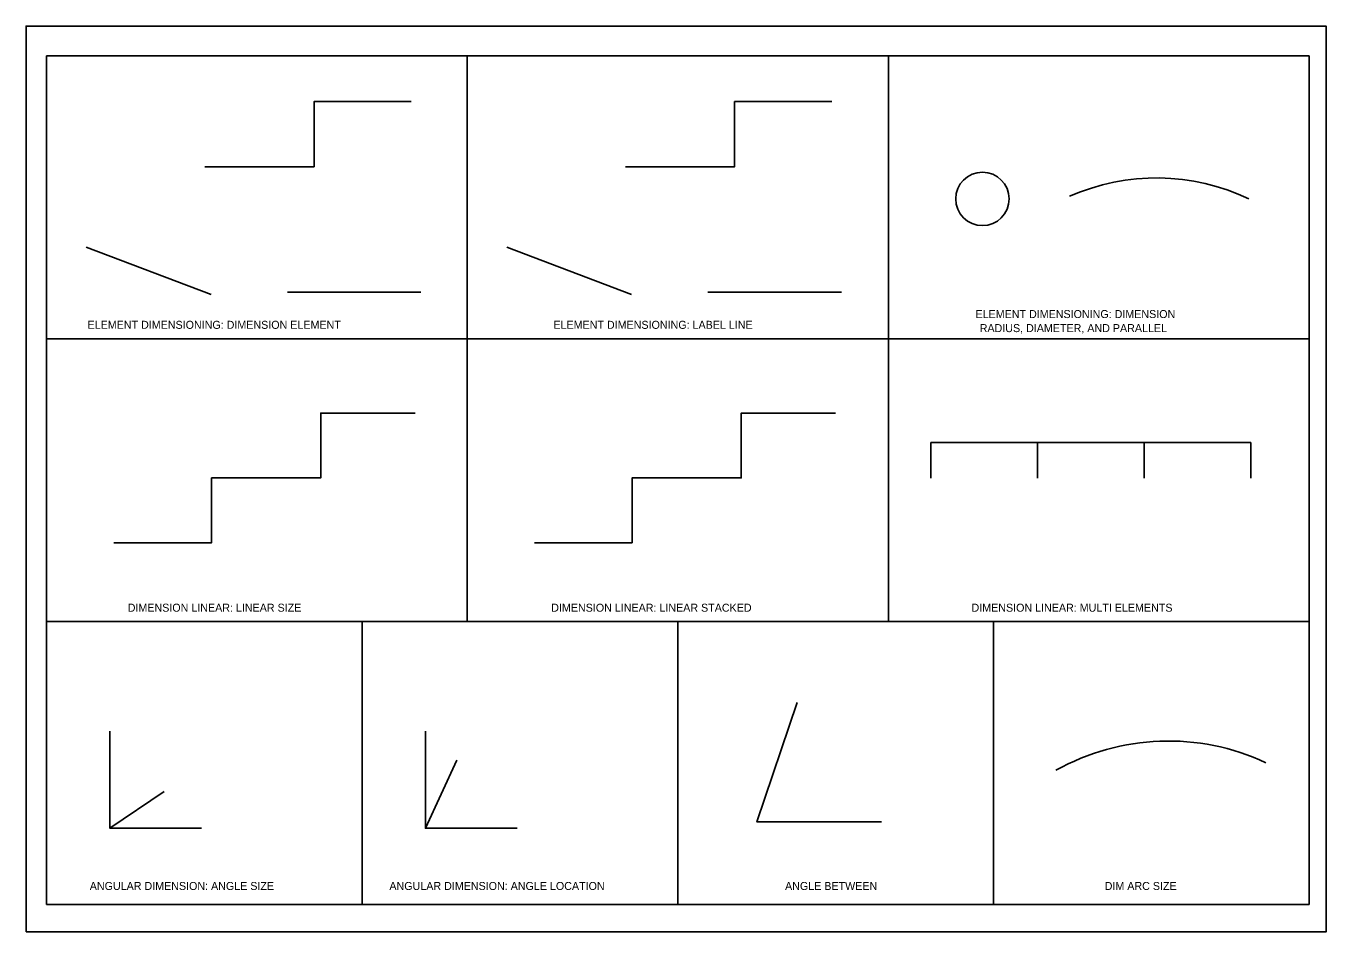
# Model space of a CAD drawing. Extents: x -558 to 904, y -348 to 671.
import ezdxf

# ---------------------------------------------------------------- set-up
doc = ezdxf.new("R2010")
doc.units = 0
doc.layers.add('Draft_Named_Boundary', color=7, linetype='Continuous')
doc.layers.add('Level 1', color=7, linetype='Continuous')

msp = doc.modelspace()

# ---------------------------------------------------------------- linework, layer by layer
at = {"layer": 'Draft_Named_Boundary'}
msp.add_lwpolyline([(-558.2, -347.7), (903.9, -347.7), (903.9, 671), (-558.2, 671)], close=True, dxfattribs=at)
at = {"layer": 'Level 1'}
for p, q in [((-535.2, 637.5), (-535.2, -316.7)), ((884.8, 637.5), (-535.2, 637.5)), ((-62.2, 637.5), (-62.2, 1.3)), ((411.8, 637.5), (411.8, 1.3)), ((884.8, 637.5), (884.8, -316.7)), ((-490.4, 422.3), (-350.1, 369.1)), ((-17.4, 422.3), (122.9, 369.1)), ((-264.2, 371.9), (-114.2, 371.9)), ((208.8, 371.9), (358.8, 371.9)), ((884.8, 319.4), (-535.2, 319.4)), ((459.4, 202.6), (819.4, 202.6)), ((459.4, 202.6), (459.4, 162.6)), ((579.4, 202.6), (579.4, 162.6)), ((699.4, 202.6), (699.4, 162.6)), ((819.4, 202.6), (819.4, 162.6)), ((-535.2, 1.3), (884.8, 1.3)), ((-180.2, 1.3), (-180.2, -316.7)), ((174.8, 1.3), (174.8, -316.7)), ((529.8, 1.3), (529.8, -316.7)), ((-108.9, -231), (-73.8, -154.5)), ((-463.9, -231), (-402.7, -189.8)), ((-535.2, -316.7), (884.8, -316.7))]:
    msp.add_line(p, q, dxfattribs=at)
for points in [[(-357.1, 512.7), (-234.3, 512.7), (-234.3, 586.1), (-125, 586.1)], [(115.9, 512.7), (238.7, 512.7), (238.7, 586.1), (348, 586.1)], [(-459.3, 89.9), (-349.5, 89.9), (-349.5, 162.8), (-226.8, 162.8), (-226.8, 235.7), (-120.7, 235.7)], [(13.7, 89.9), (123.5, 89.9), (123.5, 162.8), (246.2, 162.8), (246.2, 235.7), (352.3, 235.7)], [(309.3, -89.8), (263.9, -224), (403.8, -224)], [(-463.9, -121.9), (-463.9, -231), (-360.7, -231)], [(-108.9, -121.9), (-108.9, -231), (-5.7, -231)]]:
    msp.add_lwpolyline(points, dxfattribs=at)
msp.add_circle((517.5, 476.6), 30, dxfattribs=at)
for centre, radius, start, end in [((713.1, 259.4), 240.8, 64.4039, 113.9177), ((726.6, -392.5), 259.5, 64.9836, 119.1896)]:
    msp.add_arc(centre, radius, start, end, dxfattribs=at)

# ---------------------------------------------------------------- texts
for s, p in [('ELEMENT DIMENSIONING: DIMENSION ', (509.7, 342.6)), ('ELEMENT DIMENSIONING: DIMENSION ELEMENT', (-489, 330.5)), ('ELEMENT DIMENSIONING: LABEL LINE', (35, 330.5)), ('RADIUS, DIAMETER, AND PARALLEL', (514.4, 326.8)), ('DIMENSION LINEAR: LINEAR SIZE', (-443.8, 12.4)), ('DIMENSION LINEAR: LINEAR STACKED', (32.5, 12.4)), ('DIMENSION LINEAR: MULTI ELEMENTS', (505.2, 12.4)), ('ANGULAR DIMENSION: ANGLE SIZE', (-486.5, -300.5)), ('ANGULAR DIMENSION: ANGLE LOCATION', (-149.5, -300.5)), ('ANGLE BETWEEN', (295.5, -300.5)), ('DIM ARC SIZE', (655, -300.5))]:
    msp.add_text(s, height=9, dxfattribs=at).set_placement(p)

doc.saveas('drawing.dxf')
